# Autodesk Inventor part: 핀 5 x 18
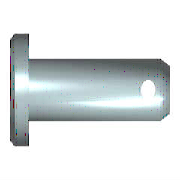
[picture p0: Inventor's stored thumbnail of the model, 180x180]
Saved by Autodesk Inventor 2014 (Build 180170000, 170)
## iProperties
Created: 2012-02
Part Number: 핀 5 x 18
Material: 강철
Description: 머리가 있는 클레비스 핀
Document SubType Name: Modeling
Standard: ISO 2341
Designer: test
Standard Revision: Second edition 1986-11-01
Standards Organization: ISO
Language: ko-KR
Size Designation: B - 5 x 18
Categories: <MemberInstance><Categories><Category DisplayName="조임쇠" InternalName="e4da775c-781d-43d5-af7c-5136215cf5a6" Mnemonic="FSTN"><Category DisplayName="핀" InternalNa
Density: 7.85 g/cm^3
Appearance: 강철
IsCustomPart: 1
Author: test
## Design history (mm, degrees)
sketch "스케치1"
  geometry: L1 (-1.6, 0)-(-1.6, 4); L2 (-1.6, 4)-(0, 4); L3 (0, 4)-(0, 2.5); L4 (0, 2.5)-(18, 2.5); L5 (18, 2.5)-(18, 0); L6 (-1.6, 0)-(18, 0); L7 (-4, 0)-(17, 0) reference; L8 (0, -0.98)-(0, 3.08) reference; C1 r 0.6 at (15.1, 0)
  constraints: 12 end point, 3 parallel, 2 collinear, 2 perpendicular, 1 centre point, 1 point on line, 1 vertical
  dimensions: "d0" = 5 diameter of L4 L6 (= NND); "d1" = 8 diameter of L2 L6 (= KOD); "d2" = 1.6 distance of L1.end L2.end (= KOH); "d3" = 18 distance of L3.end L4.end (= NLG); "d5" = 2.9 distance from line of L5 C1.centre (= DIST); "d6" = 1.2 diameter of C1 (= BOR)
revolve "본체" stored, may be unused: angle "d4" = 90 deg
extrude "구멍" cut sketch "스케치1" stored distance "d7" = 5 (= NND); taper "d8" = 0 deg
workaxis "Work Axis1"
workplane "Work Plane1"
body "Solid1"
chamfer "모따기1" distance "d9" = 1 (= PHH2); stored, may be unused: angle "d10" = 45 deg (= FAWI2), second distance "d16" = 1 (= PHH2)
chamfer "모따기2" distance "d11" = 2 (= PHH1); stored, may be unused: angle "d12" = 30 deg (= FAWI1), second distance "d17" = 2 (= PHH1)
other parameters: "PHH1" = 2 [user parameter; used in 2 equation terms], "PHH2" = 1 [user parameter; used in 2 equation terms], "KOD" = 8 [user parameter; used in 1 equation term], "KOH" = 1.6 [user parameter; used in 1 equation term], "NND" = 5 [user parameter; used in 2 equation terms], "FAWI1" = 30 deg [user parameter; used in 1 equation term], "FAWI2" = 45 deg [user parameter; used in 1 equation term], "DIST" = 2.9 [user parameter; used in 1 equation term], "BOR" = 1.2 [user parameter; used in 1 equation term], "NLG" = 18 [user parameter; used in 1 equation term], "d13" = 0, "d14" = 0, "d27" = 0, "d28" = 0, "d29" = 0, "d30" = 0, "d31" = 0
